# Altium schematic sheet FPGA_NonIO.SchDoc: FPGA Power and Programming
size A4; Organization: Altium Limited.; Address1: Level 3, 12a Rodborough Rd; Address2: Frenchs Forest 2086; Address3: NSW; Address4: AUSTRALIA; SheetNumber: 7; SheetTotal: 21
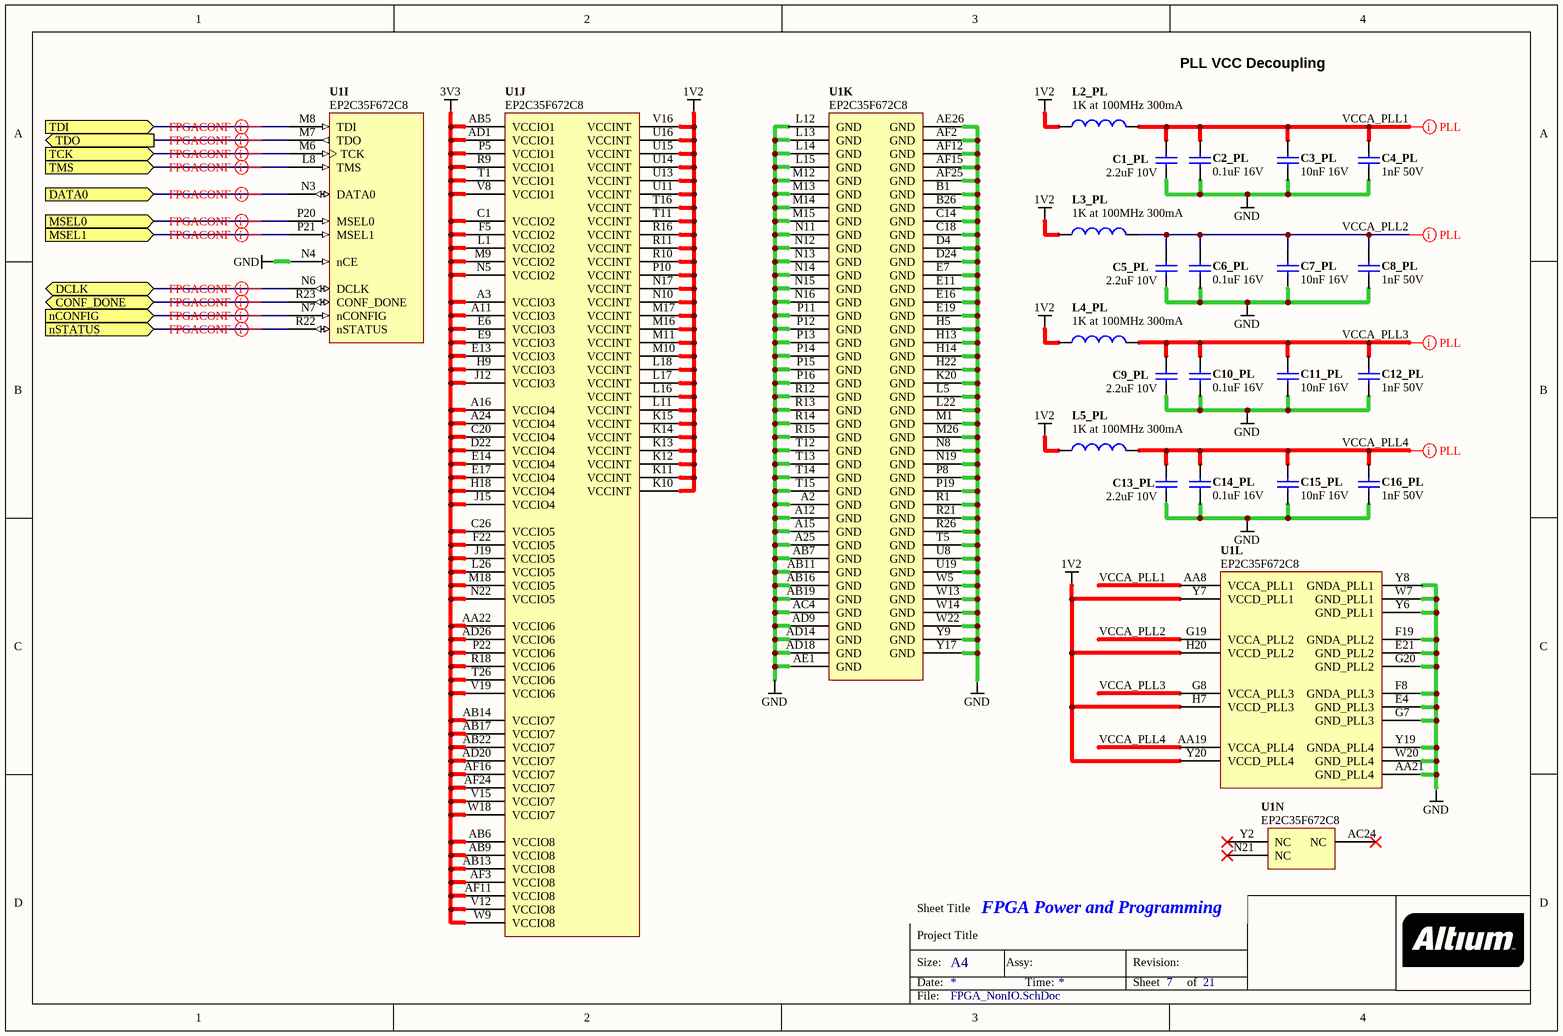
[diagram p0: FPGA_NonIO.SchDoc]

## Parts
C1_PL  2.2uF 10V  [CAPC1608-STAR]
C2_PL  0.1uF 16V  [CAPC1005-STAR]
C3_PL  10nF 16V  [CAPC1005-STAR]
C4_PL  1nF 50V  [CAPC1005-STAR]
C5_PL  2.2uF 10V  [CAPC1608-STAR]
C6_PL  0.1uF 16V  [CAPC1005-STAR]
C7_PL  10nF 16V  [CAPC1005-STAR]
C8_PL  1nF 50V  [CAPC1005-STAR]
C9_PL  2.2uF 10V  [CAPC1608-STAR]
C10_PL  0.1uF 16V  [CAPC1005-STAR]
C11_PL  10nF 16V  [CAPC1005-STAR]
C12_PL  1nF 50V  [CAPC1005-STAR]
C13_PL  2.2uF 10V  [CAPC1608-STAR]
C14_PL  0.1uF 16V  [CAPC1005-STAR]
C15_PL  10nF 16V  [CAPC1005-STAR]
C16_PL  1nF 50V  [CAPC1005-STAR]
L2_PL  1K at 100MHz 300mA  [INDC2012-STAR]
L3_PL  1K at 100MHz 300mA  [INDC2012-STAR]
L4_PL  1K at 100MHz 300mA  [INDC2012-STAR]
L5_PL  1K at 100MHz 300mA  [INDC2012-STAR]
U1  EP2C35F672C8  [BGA100P26X26-672]  (parts I,J,K,L,N of 14)

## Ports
CONF_DONE (bidir), DATA0 (in), DCLK (bidir), MSEL0 (in), MSEL1 (in), nCONFIG (in), nSTATUS (in), TCK (in), TDI (in), TDO (out), TMS (in)

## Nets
1V2: L2_PL.1 L3_PL.1 L4_PL.1 L5_PL.1 U1.H7(VCCD_PLL3) U1.H20(VCCD_PLL2) U1.K10(VCCINT) U1.K11(VCCINT) U1.K12(VCCINT) U1.K13(VCCINT) U1.K14(VCCINT) U1.K15(VCCINT) U1.L11(VCCINT) U1.L16(VCCINT) U1.L17(VCCINT) U1.L18(VCCINT) U1.M10(VCCINT) U1.M11(VCCINT) U1.M16(VCCINT) U1.M17(VCCINT) U1.N10(VCCINT) U1.N17(VCCINT) U1.P10(VCCINT) U1.R10(VCCINT) U1.R11(VCCINT) U1.R16(VCCINT) U1.T11(VCCINT) U1.T16(VCCINT) U1.U11(VCCINT) U1.U13(VCCINT) U1.U14(VCCINT) U1.U15(VCCINT) U1.U16(VCCINT) U1.V16(VCCINT) U1.Y7(VCCD_PLL1) U1.Y20(VCCD_PLL4)
3V3: U1.A3(VCCIO3) U1.A11(VCCIO3) U1.A16(VCCIO4) U1.A24(VCCIO4) U1.AA22(VCCIO6) U1.AB5(VCCIO1) U1.AB6(VCCIO8) U1.AB9(VCCIO8) U1.AB13(VCCIO8) U1.AB14(VCCIO7) U1.AB17(VCCIO7) U1.AB22(VCCIO7) U1.AD1(VCCIO1) U1.AD20(VCCIO7) U1.AD26(VCCIO6) U1.AF3(VCCIO8) U1.AF11(VCCIO8) U1.AF16(VCCIO7) U1.AF24(VCCIO7) U1.C1(VCCIO2) U1.C20(VCCIO4) U1.C26(VCCIO5) U1.D22(VCCIO4) U1.E6(VCCIO3) U1.E9(VCCIO3) U1.E13(VCCIO3) U1.E14(VCCIO4) U1.E17(VCCIO4) U1.F5(VCCIO2) U1.F22(VCCIO5) U1.H9(VCCIO3) U1.H18(VCCIO4) U1.J12(VCCIO3) U1.J15(VCCIO4) U1.J19(VCCIO5) U1.L1(VCCIO2) U1.L26(VCCIO5) U1.M9(VCCIO2) U1.M18(VCCIO5) U1.N5(VCCIO2) U1.N22(VCCIO5) U1.P5(VCCIO1) U1.P22(VCCIO6) U1.R9(VCCIO1) U1.R18(VCCIO6) U1.T1(VCCIO1) U1.T26(VCCIO6) U1.V8(VCCIO1) U1.V12(VCCIO8) U1.V15(VCCIO7) U1.V19(VCCIO6) U1.W9(VCCIO8) U1.W18(VCCIO7)
GND: C1_PL.2 C2_PL.2 C3_PL.2 C4_PL.2 C5_PL.2 C6_PL.2 C7_PL.2 C8_PL.2 C9_PL.2 C10_PL.2 C11_PL.2 C12_PL.2 C13_PL.2 C14_PL.2 C15_PL.2 C16_PL.2 U1.A2(GND) U1.A12(GND) U1.A15(GND) U1.A25(GND) U1.AA21(GND_PLL4) U1.AB7(GND) U1.AB11(GND) U1.AB16(GND) U1.AB19(GND) U1.AC4(GND) U1.AD9(GND) U1.AD14(GND) U1.AD18(GND) U1.AE1(GND) U1.AE26(GND) U1.AF2(GND) U1.AF12(GND) U1.AF15(GND) U1.AF25(GND) U1.B1(GND) U1.B26(GND) U1.C14(GND) U1.C18(GND) U1.D4(GND) U1.D24(GND) U1.E4(GND_PLL3) U1.E7(GND) U1.E11(GND) U1.E16(GND) U1.E19(GND) U1.E21(GND_PLL2) U1.F8(GNDA_PLL3) U1.F19(GNDA_PLL2) U1.G7(GND_PLL3) U1.G20(GND_PLL2) U1.H5(GND) U1.H13(GND) U1.H14(GND) U1.H22(GND) U1.K20(GND) U1.L5(GND) U1.L12(GND) U1.L13(GND) U1.L14(GND) U1.L15(GND) U1.L22(GND) U1.M1(GND) U1.M12(GND) U1.M13(GND) U1.M14(GND) U1.M15(GND) U1.M26(GND) U1.N4(nCE) U1.N8(GND) U1.N11(GND) U1.N12(GND) U1.N13(GND) U1.N14(GND) U1.N15(GND) U1.N16(GND) U1.N19(GND) U1.P8(GND) U1.P11(GND) U1.P12(GND) U1.P13(GND) U1.P14(GND) U1.P15(GND) U1.P16(GND) U1.P19(GND) U1.R1(GND) U1.R12(GND) U1.R13(GND) U1.R14(GND) U1.R15(GND) U1.R21(GND) U1.R26(GND) U1.T5(GND) U1.T12(GND) U1.T13(GND) U1.T14(GND) U1.T15(GND) U1.U8(GND) U1.U19(GND) U1.W5(GND) U1.W7(GND_PLL1) U1.W13(GND) U1.W14(GND) U1.W20(GND_PLL4) U1.W22(GND) U1.Y6(GND_PLL1) U1.Y8(GNDA_PLL1) U1.Y9(GND) U1.Y17(GND) U1.Y19(GNDA_PLL4)
CONF_DONE: U1.R23(CONF_DONE) ; port CONF_DONE
DATA0: U1.N3(DATA0) ; port DATA0
DCLK: U1.N6(DCLK) ; port DCLK
MSEL0: U1.P20(MSEL0) ; port MSEL0
MSEL1: U1.P21(MSEL1) ; port MSEL1
nCONFIG: U1.N7(nCONFIG) ; port nCONFIG
nSTATUS: U1.R22(nSTATUS) ; port nSTATUS
TCK: U1.M6(TCK) ; port TCK
TDI: U1.M8(TDI) ; port TDI
TDO: U1.M7(TDO) ; port TDO
TMS: U1.L8(TMS) ; port TMS
VCCA_PLL1: C1_PL.1 C2_PL.1 C3_PL.1 C4_PL.1 L2_PL.2 U1.AA8(VCCA_PLL1)
VCCA_PLL2: C5_PL.1 C6_PL.1 C7_PL.1 C8_PL.1 L3_PL.2 U1.G19(VCCA_PLL2)
VCCA_PLL3: C9_PL.1 C10_PL.1 C11_PL.1 C12_PL.1 L4_PL.2 U1.G8(VCCA_PLL3)
VCCA_PLL4: C13_PL.1 C14_PL.1 C15_PL.1 C16_PL.1 L5_PL.2 U1.AA19(VCCA_PLL4)

Not connected (* = marked no-connect by the designer): U1 AC24(NC)* N21(NC)* Y2(NC)*

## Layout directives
net class FPGACONF: CONF_DONE, DATA0, DCLK, MSEL0, MSEL1, nCONFIG, nSTATUS, TCK, TDI, TDO, TMS
net class PLL: VCCA_PLL1, VCCA_PLL2, VCCA_PLL3, VCCA_PLL4

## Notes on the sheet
- PLL VCC Decoupling

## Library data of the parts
C1_PL C5_PL C9_PL C13_PL = D-101-0095: Capacitor, Ceramic, 2.2uF 10% 10V 0603 (1608) X5R; Polarity: Non-Polarized
C2_PL C6_PL C10_PL C14_PL = D-101-0080: Capacitor, Ceramic, 0.1uF 10% 16V 0402 (1005) X7R; Polarity: Non-Polarized
C3_PL C7_PL C11_PL C15_PL = D-101-0077: Capacitor, Ceramic, 10nF 10% 16V 0402 (1005) X7R; Polarity: Non-Polarized
C4_PL C8_PL C12_PL C16_PL = D-101-0030: Capacitor, Ceramic, 1nF 10% 50V 0402 (1005) X7R; Polarity: Non-Polarized
L2_PL L3_PL L4_PL L5_PL = D-102-0002: Inductor, Ferrite Bead 1K@100MHz 300mA 0805 (2012) BMB2A1000LN2; Inductance: nH
U1 = D-241-0004: FPGA, Altera Cyclone2-35 F672; Supply Voltage: mV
